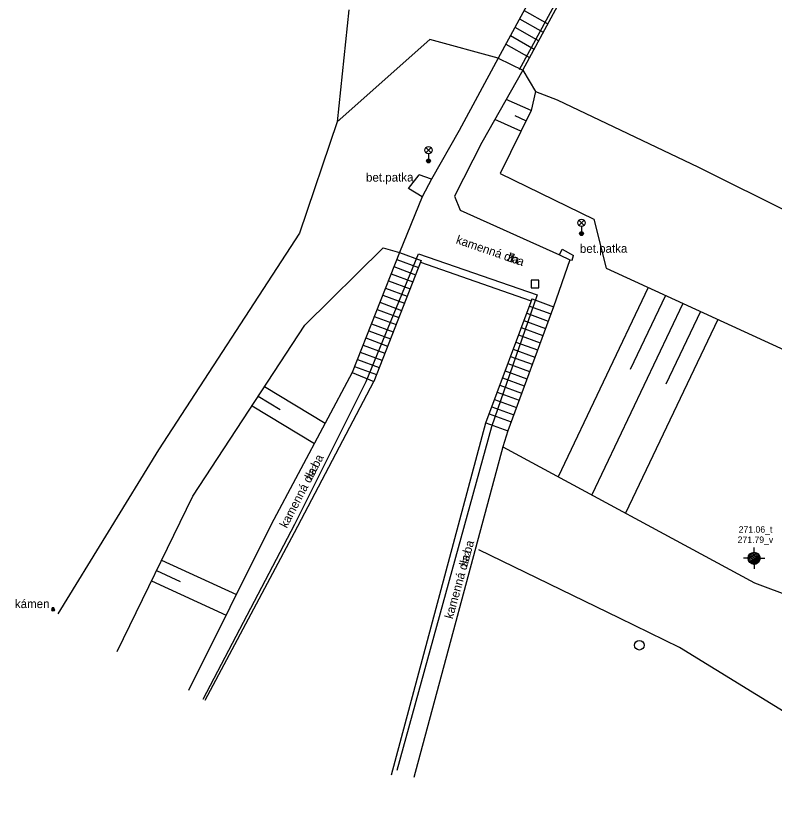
# Model space of a CAD drawing. Extents: x -517955 to -517507, y -1177194 to -1176857.
# Drawn here: x -517772.02 to -517732.44, y -1177027.23 to -1176986.39 of the extents above; entities that cross this region are included whole.
import ezdxf

# ---------------------------------------------------------------- set-up
doc = ezdxf.new("R2010")
doc.units = 0
for name, color, linetype in [('chodníky_obrubnik_schody', 7, 'Continuous'), ('hrany svahu', 7, 'Continuous'), ('mapove znacky', 7, 'Continuous'), ('Ploty', 7, 'Continuous'), ('porost', 7, 'Continuous'), ('Povrchy_popis', 7, 'Continuous'), ('Zabradli', 7, 'Continuous'), ('šrafy', 7, 'Continuous')]:
    doc.layers.add(name, color=color, linetype=linetype)

msp = doc.modelspace()

# ---------------------------------------------------------------- linework, layer by layer
at = {"layer": 'chodníky_obrubnik_schody'}
for p, q in [((-517738.31, -1176972.94), (-517746.85, -1176988.6)), ((-517745.56, -1176989.23), (-517737.11, -1176973.62)), ((-517745.493, -1176986.111), (-517744.252, -1176986.814)), ((-517745.732, -1176986.55), (-517744.49, -1176987.254)), ((-517745.971, -1176986.989), (-517744.728, -1176987.693)), ((-517746.211, -1176987.428), (-517744.966, -1176988.133)), ((-517746.45, -1176987.867), (-517745.204, -1176988.573)), ((-517746.85, -1176988.6), (-517748.88, -1176992.38)), ((-517746.85, -1176988.6), (-517745.56, -1176989.23)), ((-517745.56, -1176989.23), (-517747.69, -1176993)), ((-517748.88, -1176992.38), (-517750.33, -1176994.92)), ((-517747.69, -1176993), (-517749.12, -1176995.81)), ((-517751.53, -1176995.41), (-517750.97, -1176994.69)), ((-517750.33, -1176994.92), (-517750.97, -1176994.69)), ((-517750.33, -1176994.92), (-517750.82, -1176995.85)), ((-517750.82, -1176995.85), (-517751.53, -1176995.41)), ((-517750.82, -1176995.85), (-517751.99, -1176998.74)), ((-517749.12, -1176995.81), (-517748.83, -1176996.53)), ((-517748.83, -1176996.53), (-517743.65, -1176998.87)), ((-517751.99, -1176998.74), (-517754.46, -1177005.01)), ((-517751.99, -1176998.74), (-517750.86, -1176999.16)), ((-517743.65, -1176998.87), (-517743.51, -1176998.57)), ((-517743.65, -1176998.87), (-517743.11, -1176999.13)), ((-517743.51, -1176998.57), (-517742.91, -1176998.9)), ((-517750.86, -1176999.16), (-517753.34, -1177005.47)), ((-517752.137, -1176999.112), (-517751.006, -1176999.532)), ((-517750.88, -1176999.27), (-517750.86, -1176999.16)), ((-517745.16, -1177001.27), (-517750.88, -1176999.27)), ((-517743.11, -1176999.13), (-517743.96, -1177001.58)), ((-517743.11, -1176999.13), (-517742.99, -1176999.15)), ((-517742.99, -1176999.15), (-517742.91, -1176998.9)), ((-517752.283, -1176999.484), (-517751.153, -1176999.905)), ((-517749.86, -1176999.53), (-517749.86, -1176999.53)), ((-517752.43, -1176999.857), (-517751.299, -1177000.277)), ((-517752.577, -1177000.229), (-517751.445, -1177000.649)), ((-517752.723, -1177000.601), (-517751.592, -1177001.022)), ((-517752.87, -1177000.973), (-517751.738, -1177001.394)), ((-517747.49, -1177007.64), (-517745.08, -1177001.17)), ((-517745.08, -1177001.17), (-517745.16, -1177001.27)), ((-517745.08, -1177001.17), (-517743.96, -1177001.58)), ((-517753.163, -1177001.718), (-517752.031, -1177002.139)), ((-517753.016, -1177001.346), (-517751.884, -1177001.766)), ((-517743.96, -1177001.58), (-517746.35, -1177008.06)), ((-517745.22, -1177001.545), (-517744.098, -1177001.955)), ((-517753.31, -1177002.09), (-517752.177, -1177002.511)), ((-517745.359, -1177001.92), (-517744.237, -1177002.331)), ((-517753.456, -1177002.462), (-517752.323, -1177002.883)), ((-517745.499, -1177002.295), (-517744.375, -1177002.706)), ((-517753.603, -1177002.835), (-517752.47, -1177003.256)), ((-517745.639, -1177002.669), (-517744.514, -1177003.081)), ((-517753.75, -1177003.207), (-517752.616, -1177003.628)), ((-517745.778, -1177003.044), (-517744.652, -1177003.456)), ((-517753.896, -1177003.579), (-517752.762, -1177004)), ((-517745.918, -1177003.419), (-517744.791, -1177003.832)), ((-517754.043, -1177003.951), (-517752.909, -1177004.373)), ((-517746.197, -1177004.169), (-517745.067, -1177004.582)), ((-517746.057, -1177003.794), (-517744.929, -1177004.207)), ((-517754.19, -1177004.324), (-517753.055, -1177004.745)), ((-517746.337, -1177004.544), (-517745.206, -1177004.958)), ((-517754.46, -1177005.01), (-517758.69, -1177012.94)), ((-517754.46, -1177005.01), (-517753.34, -1177005.47)), ((-517754.336, -1177004.696), (-517753.201, -1177005.117)), ((-517746.476, -1177004.918), (-517745.344, -1177005.333)), ((-517746.616, -1177005.293), (-517745.483, -1177005.708)), ((-517757.47, -1177013.35), (-517753.34, -1177005.47)), ((-517746.756, -1177005.668), (-517745.621, -1177006.083)), ((-517746.895, -1177006.043), (-517745.759, -1177006.459)), ((-517747.035, -1177006.418), (-517745.898, -1177006.834)), ((-517747.174, -1177006.793), (-517746.036, -1177007.209)), ((-517747.314, -1177007.168), (-517746.175, -1177007.585)), ((-517752.41, -1177026.01), (-517747.49, -1177007.64)), ((-517747.49, -1177007.64), (-517746.35, -1177008.06)), ((-517746.35, -1177008.06), (-517746.6, -1177008.89)), ((-517746.6, -1177008.89), (-517751.24, -1177026.14)), ((-517758.69, -1177012.94), (-517763, -1177021.61)), ((-517762.14, -1177022.1), (-517757.47, -1177013.35))]:
    msp.add_line(p, q, dxfattribs=at)
at = {"layer": 'hrany svahu'}
for p, q in [((-517750.41, -1176987.63), (-517755.24, -1176991.93)), ((-517746.85, -1176988.6), (-517750.41, -1176987.63)), ((-517745.56, -1176989.23), (-517744.9, -1176990.34)), ((-517744.9, -1176990.34), (-517745.13, -1176991.33)), ((-517744.9, -1176990.34), (-517743.77, -1176990.78)), ((-517743.77, -1176990.78), (-517736.39, -1176994.3)), ((-517745.13, -1176991.33), (-517746.75, -1176994.63)), ((-517736.39, -1176994.3), (-517718.11, -1177003.41)), ((-517746.75, -1176994.63), (-517741.86, -1176997)), ((-517741.86, -1176997), (-517741.21, -1176999.56)), ((-517756.94, -1177002.54), (-517752.85, -1176998.51)), ((-517752.85, -1176998.51), (-517751.99, -1176998.74)), ((-517741.21, -1176999.56), (-517730.83, -1177004.34)), ((-517762.77, -1177011.47), (-517756.94, -1177002.54)), ((-517746.6, -1177008.89), (-517733.48, -1177015.98)), ((-517766.73, -1177019.56), (-517762.77, -1177011.47)), ((-517733.48, -1177015.98), (-517724.07, -1177019.54))]:
    msp.add_line(p, q, dxfattribs=at)
at = {"layer": 'mapove znacky'}
for p, q in [((-517750.612, -1176993.54), (-517750.348, -1176993.275)), ((-517750.612, -1176993.275), (-517750.348, -1176993.54)), ((-517750.48, -1176993.595), (-517750.48, -1176993.97)), ((-517742.633, -1176997.33), (-517742.367, -1176997.065)), ((-517742.633, -1176997.065), (-517742.367, -1176997.33)), ((-517742.5, -1176997.385), (-517742.5, -1176997.76)), ((-517733.769, -1177014.559), (-517733.473, -1177014.389)), ((-517733.49, -1177014.387), (-517733.49, -1177014.137)), ((-517733.802, -1177014.7), (-517734.052, -1177014.7)), ((-517733.8, -1177014.657), (-517733.372, -1177014.411)), ((-517733.8, -1177014.738), (-517733.302, -1177014.451)), ((-517733.783, -1177014.809), (-517733.249, -1177014.502)), ((-517733.751, -1177014.872), (-517733.211, -1177014.561)), ((-517733.705, -1177014.927), (-517733.187, -1177014.627)), ((-517733.644, -1177014.972), (-517733.177, -1177014.703)), ((-517733.56, -1177015.005), (-517733.192, -1177014.792)), ((-517733.177, -1177014.7), (-517732.927, -1177014.7)), ((-517733.49, -1177015.012), (-517733.49, -1177015.262)), ((-517733.42, -1177015.005), (-517733.262, -1177014.913))]:
    msp.add_line(p, q, dxfattribs=at)
msp.add_lwpolyline([(-517745.13, -1177000.59), (-517744.73, -1177000.59), (-517744.73, -1177000.19), (-517745.13, -1177000.19)], close=True, dxfattribs=at)
for centre, radius in [((-517750.48, -1176993.407), 0.188), ((-517750.48, -1176993.97), 0.1), ((-517750.48, -1176993.97), 0.0723), ((-517750.48, -1176993.97), 0.0438), ((-517742.5, -1176997.198), 0.188), ((-517742.5, -1176997.76), 0.1), ((-517742.5, -1176997.76), 0.0723), ((-517742.5, -1176997.76), 0.0438), ((-517733.49, -1177014.7), 0.312), ((-517770.07, -1177017.4), 0.0683), ((-517770.07, -1177017.4), 0.0119), ((-517739.48, -1177019.24), 0.25)]:
    msp.add_circle(centre, radius, dxfattribs=at)
msp.add_arc((-517770.07, -1177017.346), 0.0652, 339.2991, 201.8798, dxfattribs=at)
at = {"layer": 'Ploty'}
for p, q in [((-517740.52, -1177017.82), (-517747.86, -1177014.26)), ((-517737.38, -1177019.35), (-517740.52, -1177017.82)), ((-517724.61, -1177027.23), (-517737.38, -1177019.35))]:
    msp.add_line(p, q, dxfattribs=at)
at = {"layer": 'porost'}
for p, q in [((-517754.63, -1176986.08), (-517755.24, -1176991.93)), ((-517755.24, -1176991.93), (-517757.21, -1176997.73)), ((-517757.21, -1176997.73), (-517764.57, -1177009.04)), ((-517764.57, -1177009.04), (-517769.82, -1177017.61))]:
    msp.add_line(p, q, dxfattribs=at)
at = {"layer": 'Zabradli'}
for p, q in [((-517737.29, -1176973.66), (-517745.75, -1176989.22)), ((-517753.73, -1177005.47), (-517751, -1176998.82)), ((-517751, -1176998.82), (-517744.82, -1177000.95)), ((-517744.82, -1177000.95), (-517747.2, -1177007.84)), ((-517757.45, -1177012.92), (-517753.73, -1177005.47)), ((-517747.2, -1177007.84), (-517752.14, -1177025.77)), ((-517762.24, -1177022.06), (-517757.45, -1177012.92))]:
    msp.add_line(p, q, dxfattribs=at)
at = {"layer": 'šrafy'}
for p, q in [((-517745.13, -1176991.33), (-517746.422, -1176990.756)), ((-517745.659, -1176992.408), (-517747.015, -1176991.805)), ((-517745.395, -1176991.869), (-517745.951, -1176991.622)), ((-517739.021, -1177000.568), (-517743.722, -1177010.445)), ((-517738.113, -1177000.986), (-517739.954, -1177004.855)), ((-517737.204, -1177001.405), (-517741.96, -1177011.397)), ((-517736.296, -1177001.823), (-517738.103, -1177005.62)), ((-517735.388, -1177002.241), (-517740.198, -1177012.349)), ((-517759.042, -1177005.739), (-517755.872, -1177007.657)), ((-517759.365, -1177006.244), (-517758.216, -1177006.94)), ((-517759.689, -1177006.75), (-517756.438, -1177008.717)), ((-517764.405, -1177014.809), (-517760.508, -1177016.596)), ((-517764.668, -1177015.348), (-517763.447, -1177015.908)), ((-517764.932, -1177015.887), (-517761.042, -1177017.671))]:
    msp.add_line(p, q, dxfattribs=at)

# ---------------------------------------------------------------- texts
at = {"layer": 'Povrchy_popis'}
for s, height, rotation, p in [('bet.patka', 0.45, 0.2396, (-517753.741, -1176995.05)), ('kamenná dla', 0.45, 341.0133, (-517749.08, -1176998.257)), ('bet.patka', 0.45, 0.2396, (-517742.58, -1176998.768)), ('ž', 0.45, 341.0133, (-517746.442, -1176999.165)), ('ba', 0.45, 341.0133, (-517746.211, -1176999.244)), ('ba', 0.45, 62.517, (-517756.245, -1177010.019)), ('32', 0.315, 62.517, (-517756.422, -1177010.35)), ('kamenná dla', 0.45, 62.517, (-517757.879, -1177013.16)), ('29', 0.315, 62.517, (-517756.595, -1177010.683)), ('ba', 0.45, 74.4412, (-517748.272, -1177014.485)), ('32', 0.315, 74.4412, (-517748.377, -1177014.846)), ('kamenná dla', 0.45, 74.4412, (-517749.221, -1177017.896)), ('29', 0.315, 74.4412, (-517748.477, -1177015.207))]:
    msp.add_text(s, height=height, rotation=rotation, dxfattribs=at).set_placement(p)
for s, height, p in [('271.06_t', 0.3375, (-517734.297, -1177013.367)), ('271.79_v', 0.3375, (-517734.351, -1177013.904)), ('kámen', 0.45, (-517772.063, -1177017.302))]:
    msp.add_text(s, height=height, dxfattribs=at).set_placement(p)

doc.saveas('drawing.dxf')
